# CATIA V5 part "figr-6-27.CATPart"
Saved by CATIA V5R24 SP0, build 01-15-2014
Part number: Part1
Bounding box of the stored display mesh (mm): x -150 to 0, y -70 to 60, z -20 to 40
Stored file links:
  D:\KAVITA\CATIA V5-6R2014 Project_ Kavita\CATIA V5-6R2014_partfiles\Partfiles\c06_catia_v5-6r2014_prt\figr-6-27.CATPart
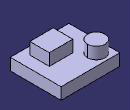
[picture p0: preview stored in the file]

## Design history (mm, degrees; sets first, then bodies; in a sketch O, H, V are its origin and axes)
Body1 (main body)
  Sketch1 on yz-plane, origin (0, 0, 0), H (0, 1, 0), V (0, 0, 1)
    line L1 (-70, 10) -> (60, 10)
    line L2 (60, 10) -> (60, -20)
    line L3 (60, -20) -> (-70, -20)
    line L4 (-70, -20) -> (-70, 10)
    horizontal: L1 H, L3 H
    vertical: L2 V, L4 V
  Pad1: profile Sketch1, direction (-1, 0, 0), length 150
  Sketch2 on face of Pad1 from Sketch1.L1, origin (0, 0, 10), H (1, 0, 0), V (0, 1, 0)
    circle A1 centre (-120, 30) radius 22.3607
  Pad2: profile Sketch2, direction (0, 0, 1), length 30
  Sketch3 on face of Pad1 from Sketch1.L1, origin (0, 0, 10), H (1, 0, 0), V (0, 1, 0)
    point P1 (-90, 0)
    line L1 (-90, 0) -> (-30, 0)
    line L2 (-30, 0) -> (-30, -50)
    line L3 (-30, -50) -> (-90, -50)
    line L4 (-90, -50) -> (-90, 0)
    coincidence: P1 H
    horizontal: L1 H, L3 H
    vertical: L2 V, L4 V
  Pad3: profile Sketch3, direction (0, 0, 1), length 30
